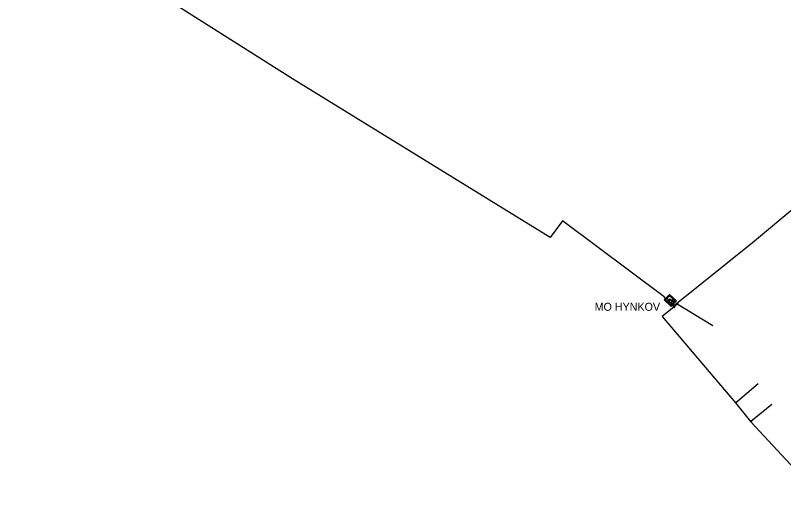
# Model space of a CAD drawing. Extents: x -555402 to -551688, y -1113264 to -1110870.
# Drawn here: x -552377.5 to -552137.6, y -1112559.7 to -1112404.3 of the extents above; entities that cross this region are included whole.
import ezdxf

# ---------------------------------------------------------------- set-up
doc = ezdxf.new("R2010")
doc.units = 0
for name, color, linetype in [('025PE', 7, 'Continuous'), ('080LT', 7, 'Continuous'), ('100PE', 7, 'Continuous'), ('100PVC', 7, 'Continuous'), ('armatury', 7, 'Continuous'), ('objekt-vhs', 7, 'Continuous'), ('Popis objektů', 7, 'Continuous')]:
    doc.layers.add(name, color=color, linetype=linetype)

msp = doc.modelspace()

# ---------------------------------------------------------------- linework, layer by layer
at = {"layer": '025PE'}
for points in [[(-552171, -1112494.36), (-552170.81, -1112494.48), (-552159.68, -1112501.26)], [(-552152.68, -1112525.35), (-552145.52, -1112519.36)], [(-552147.94, -1112531.23), (-552141.32, -1112525.81)]]:
    msp.add_lwpolyline(points, dxfattribs=at)
at = {"layer": '080LT'}
msp.add_lwpolyline([(-552173.64, -1112493.48), (-552173.47, -1112493.29), (-552173.11, -1112492.9), (-552172.26, -1112493.68), (-552172.61, -1112494.07), (-552172.78, -1112494.26)], dxfattribs=at)
at = {"layer": '100PE'}
msp.add_line((-552172.41, -1112494.59), (-552171.64, -1112495.11), dxfattribs=at)
for points in [[(-552171, -1112494.36), (-552147.27, -1112475.28), (-552132.85, -1112463.17), (-552116.13, -1112446.12), (-552101.23, -1112431.03), (-552085.17, -1112416.55), (-552071.73, -1112439), (-552062.29, -1112455.35), (-552056.08, -1112464.72), (-552048.19, -1112473.51), (-552038.74, -1112481.31)], [(-552171.64, -1112495.11), (-552171.82, -1112495.37), (-552175.49, -1112498.39), (-552152.68, -1112525.35), (-552147.94, -1112531.23), (-552121.51, -1112559.66)], [(-552171.64, -1112495.11), (-552171.43, -1112494.92), (-552171, -1112494.36)]]:
    msp.add_lwpolyline(points, dxfattribs=at)
at = {"layer": '100PVC'}
msp.add_line((-552172.41, -1112494.59), (-552172.78, -1112494.26), dxfattribs=at)
for points in [[(-552174.45, -1112492.74), (-552174.92, -1112492.3), (-552206.6, -1112468.48), (-552210.51, -1112473.77), (-552290.98, -1112424.21), (-552667.88, -1112185.67), (-552760.77, -1112122.08), (-552949.77, -1111987.23), (-553148.25, -1111845.03), (-553406.33, -1111656.91), (-553418.47, -1111647.13), (-553448.91, -1111617.6), (-553605.2, -1111415.03), (-553634.99, -1111380.49), (-553655.38, -1111359.65), (-553665.52, -1111352.95), (-553666.37, -1111352.43)], [(-552173.64, -1112493.48), (-552174.18, -1112492.98), (-552174.45, -1112492.74)], [(-552172.78, -1112494.26), (-552173.37, -1112493.72), (-552173.64, -1112493.48)]]:
    msp.add_lwpolyline(points, dxfattribs=at)
at = {"layer": 'armatury'}
for p, q in [((-552172.45, -1112493.27), (-552172.37, -1112493.27)), ((-552172.37, -1112493.27), (-552172.37, -1112493.44))]:
    msp.add_line(p, q, dxfattribs=at)
for points in [[(-552173.35, -1112493.54), (-552173.59, -1112493.04), (-552173.35, -1112493.04), (-552173.59, -1112493.54)], [(-552173.25, -1112493.97), (-552173.49, -1112493.47), (-552173.25, -1112493.47), (-552173.49, -1112493.97)], [(-552172.49, -1112494.32), (-552172.73, -1112493.82), (-552172.49, -1112493.82), (-552172.73, -1112494.32)]]:
    msp.add_lwpolyline(points, close=True, dxfattribs=at)
for points in [[(-552172.95, -1112493.27), (-552172.95, -1112493.15), (-552172.7, -1112493.27)], [(-552172.7, -1112493.27), (-552172.95, -1112493.39), (-552172.95, -1112493.27)], [(-552172.45, -1112493.27), (-552172.45, -1112493.15), (-552172.7, -1112493.27)], [(-552172.7, -1112493.27), (-552172.45, -1112493.39), (-552172.45, -1112493.27)], [(-552172.37, -1112493.44), (-552172.7, -1112493.44), (-552172.7, -1112493.27)], [(-552171.82, -1112495.37), (-552172.08, -1112495.28), (-552172, -1112495.19)], [(-552172, -1112495.19), (-552171.91, -1112495.11), (-552171.82, -1112495.37)], [(-552171.43, -1112494.92), (-552171.69, -1112494.83), (-552171.61, -1112494.74)], [(-552171.61, -1112494.74), (-552171.52, -1112494.66), (-552171.43, -1112494.92)], [(-552171.25, -1112495.1), (-552171.17, -1112495.01), (-552171.43, -1112494.92)], [(-552171.43, -1112494.92), (-552171.34, -1112495.18), (-552171.25, -1112495.1)], [(-552170.81, -1112494.48), (-552171.07, -1112494.57), (-552170.99, -1112494.66)], [(-552170.99, -1112494.66), (-552170.9, -1112494.74), (-552170.81, -1112494.48)], [(-552170.81, -1112494.48), (-552170.72, -1112494.22), (-552170.63, -1112494.3)], [(-552170.63, -1112494.3), (-552170.55, -1112494.39), (-552170.81, -1112494.48)], [(-552171.64, -1112495.55), (-552171.56, -1112495.46), (-552171.82, -1112495.37)], [(-552171.82, -1112495.37), (-552171.73, -1112495.63), (-552171.64, -1112495.55)], [(-552152.53, -1112525.22), (-552152.79, -1112525.13), (-552152.71, -1112525.04)], [(-552152.71, -1112525.04), (-552152.62, -1112524.96), (-552152.53, -1112525.22)], [(-552152.35, -1112525.4), (-552152.27, -1112525.31), (-552152.53, -1112525.22)], [(-552152.53, -1112525.22), (-552152.44, -1112525.48), (-552152.35, -1112525.4)], [(-552147.78, -1112531.1), (-552148.04, -1112531.01), (-552147.96, -1112530.92)], [(-552147.96, -1112530.92), (-552147.87, -1112530.84), (-552147.78, -1112531.1)], [(-552147.6, -1112531.28), (-552147.52, -1112531.19), (-552147.78, -1112531.1)], [(-552147.78, -1112531.1), (-552147.69, -1112531.36), (-552147.6, -1112531.28)]]:
    msp.add_lwpolyline(points, dxfattribs=at)
at = {"layer": 'objekt-vhs'}
for points in [[(-552174.91, -1112493.23), (-552173.28, -1112491.48), (-552171.06, -1112493.51), (-552172.7, -1112495.26)], [(-552172.24, -1112493.85), (-552172.24, -1112493.25), (-552171.64, -1112493.25), (-552171.64, -1112493.85)]]:
    msp.add_lwpolyline(points, close=True, dxfattribs=at)
msp.add_lwpolyline([(-552172.41, -1112494.59), (-552172.41, -1112494.59), (-552172.68, -1112494.89), (-552174.46, -1112493.28), (-552174.18, -1112492.98), (-552173.22, -1112491.92), (-552171.45, -1112493.53), (-552172.41, -1112494.59)], dxfattribs=at)

# ---------------------------------------------------------------- texts
at = {"layer": 'Popis objektů'}
msp.add_text('MO HYNKOV', height=2.5, dxfattribs=at).set_placement((-552196.61, -1112496.62))

doc.saveas('drawing.dxf')
